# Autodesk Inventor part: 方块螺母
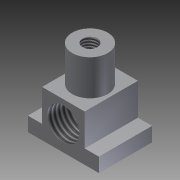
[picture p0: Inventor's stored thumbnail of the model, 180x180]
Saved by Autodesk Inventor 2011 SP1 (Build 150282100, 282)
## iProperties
Created: 2013-11
Part Number: 方块螺母
Document SubType Name: Modeling
Designer: Administrator
Density: 1 g/cm^3
Author: Administrator
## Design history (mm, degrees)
sketch "草图1"
  geometry: L1 (-20, 15)-(20, 15); L2 (20, 15)-(20, -15); L3 (20, -15)-(-20, -15); L4 (-20, -15)-(-20, 15); 3 further points
  constraints: 8 end point, 2 midpoint, 2 parallel, 1 horizontal, 1 horizontal alignment, 1 perpendicular, 1 vertical alignment
  dimensions: "d0" = 40 distance of L1.start L1.end; "d1" = 30 distance of L3.end L1.start
extrude "拉伸1" new body sketch "草图1" distance "d2" = 8; taper "d3" = 0 deg
sketch "草图2"
  geometry: L1 (-20, 15)-(20, 15) reference; L2 (-12, 15)-(12, 15); L3 (12, 15)-(12, -15); L4 (12, -15)-(-12, -15); L5 (-12, -15)-(-12, 15); 2 further points
  constraints: 8 end point, 2 midpoint, 2 parallel, 1 horizontal, 1 perpendicular
  dimensions: "d4" = 24 distance of L2.start L2.end; "d5" = 30 distance of L2.end L3.end
extrude "拉伸2" join sketch "草图2" distance "d6" = 18; taper "d7" = 0 deg
sketch "草图3"
  geometry: C1 r 10 at (0, 0); 1 further point
  constraints: 1 centre point, 1 coincident
  dimensions: "d8" = 20 diameter of C1
extrude "拉伸3" join sketch "草图3" distance "d9" = 20; taper "d10" = 0 deg
hole "Hole1" diameter "d13" = 8.376; stored, may be unused: countersink angle "d17" = 90 deg, drill point angle "d19" = 120 deg; dims "d11" = 10, "d12" = 10, "d14" = 15, "d15" = 4, "d16" = 2, "d18" = 18
hole "Hole2" diameter "d22" = 18; stored, may be unused: countersink angle "d26" = 90 deg, drill point angle "d28" = 0 deg; dims "d20" = 12, "d21" = 12, "d23" = 15, "d24" = 4, "d25" = 2, "d27" = 18
feature "螺纹1" dims "d29" = 10, "d30" = 0
node "实体1"
